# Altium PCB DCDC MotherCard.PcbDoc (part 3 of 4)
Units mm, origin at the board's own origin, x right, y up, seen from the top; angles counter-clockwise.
Board outline 252.5 x 130 mm, 6 copper layers (Top Layer, Layer 2, Layer 3, Layer 4, Layer 5, Bottom Layer), stack 1.582 mm thick; 322 components, 189 nets, 1077 pads, 1461 vias.
Unrouted connection lines stored in the file: 2.
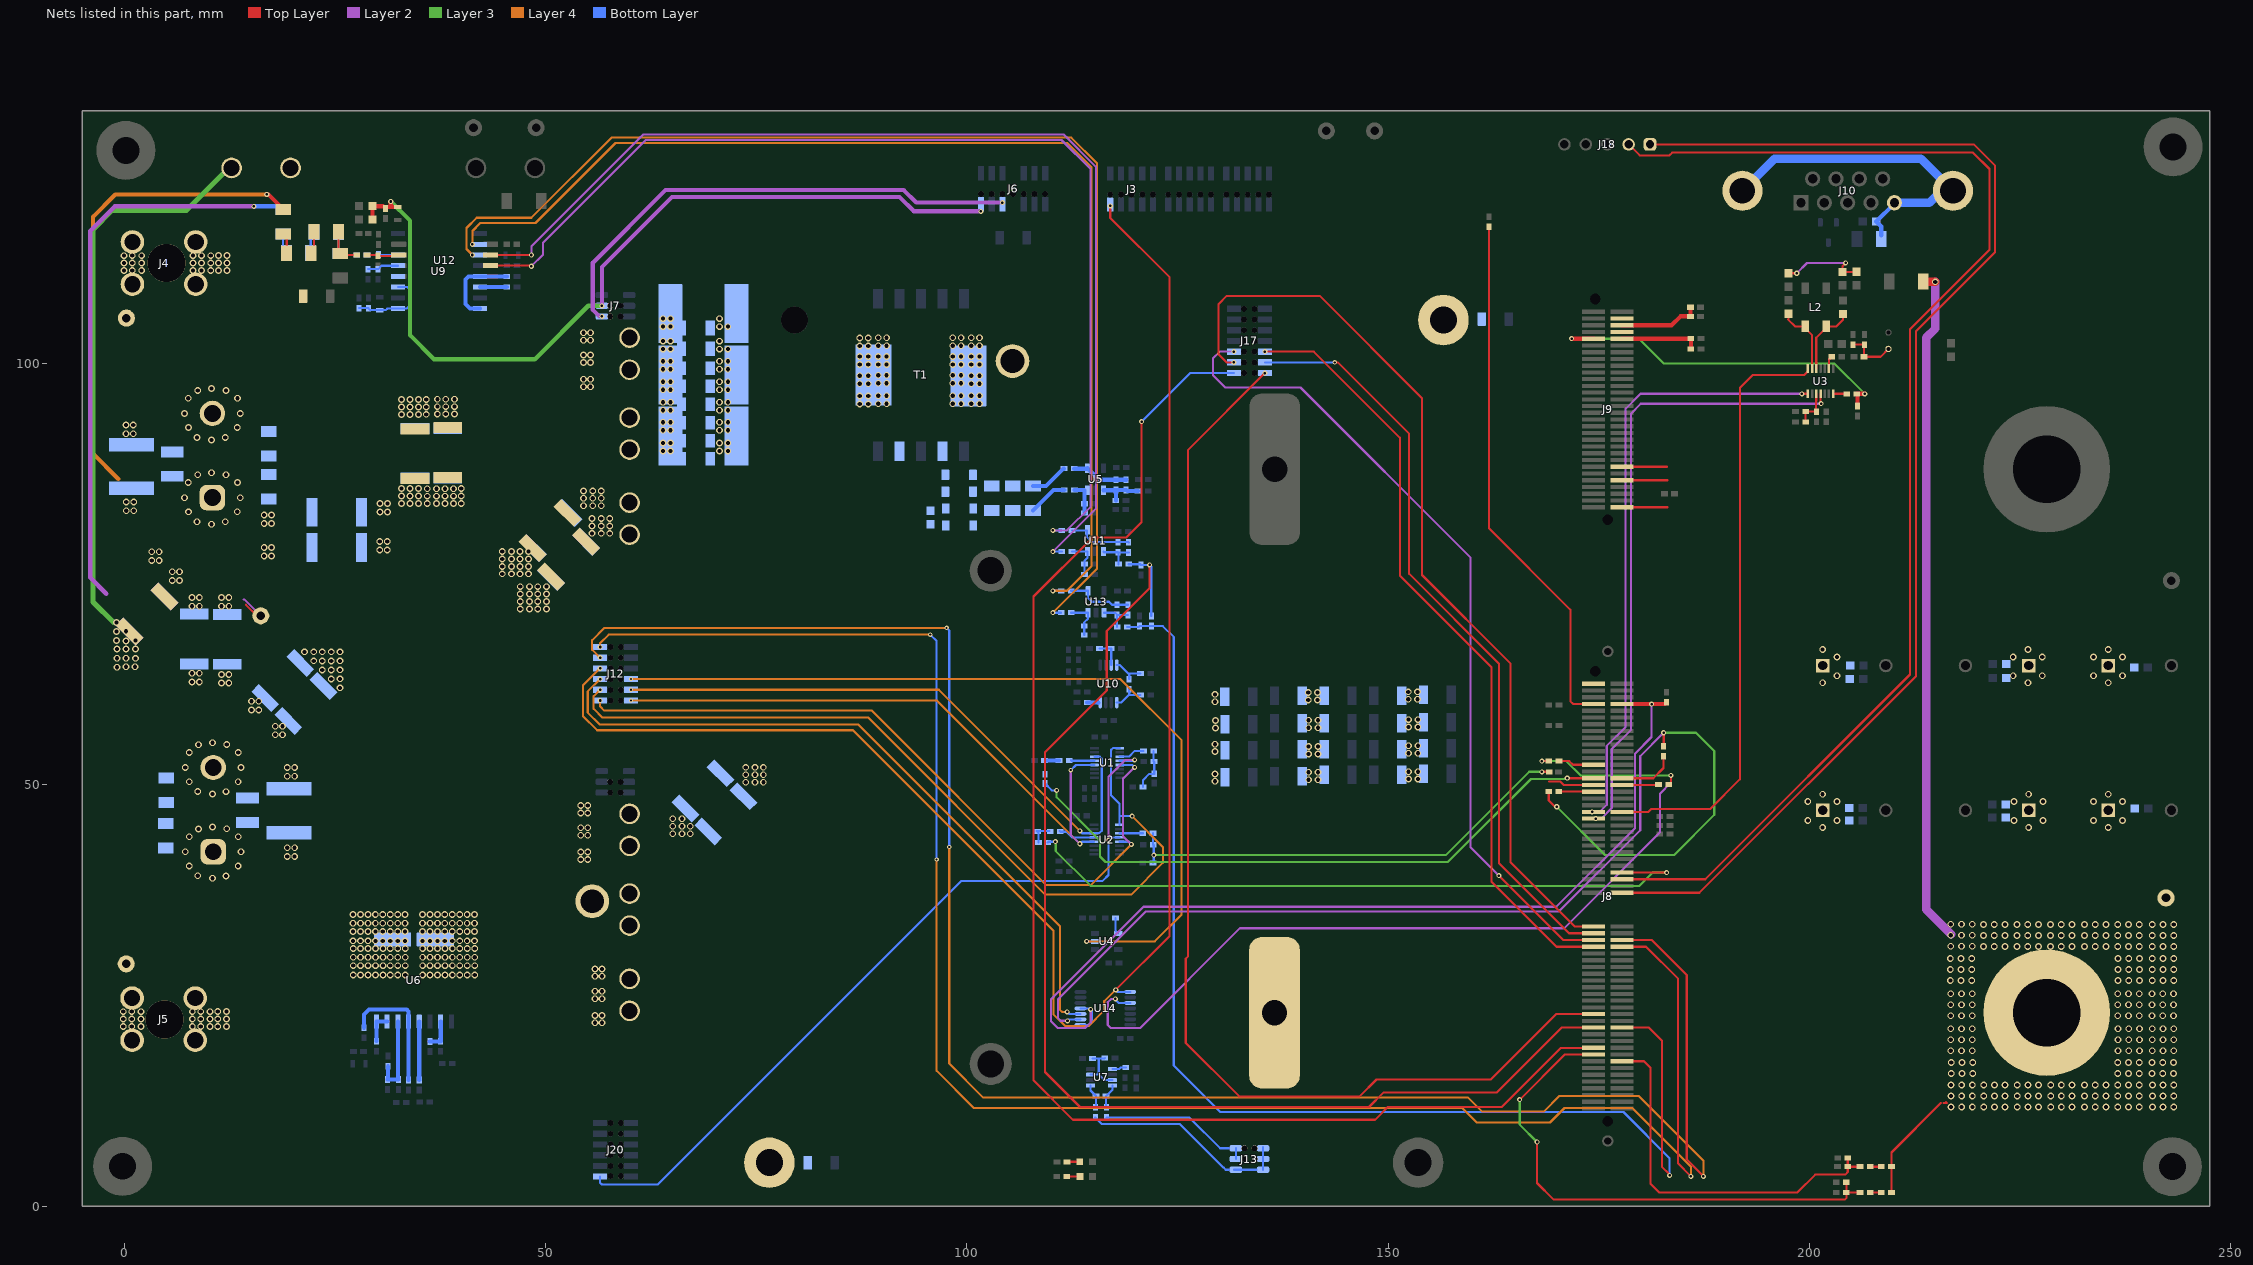
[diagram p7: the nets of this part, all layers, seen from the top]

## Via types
v1: diameter 0.8, hole 0.5, Top Layer to Bottom Layer, 1187 vias
v2: diameter 0.6, hole 0.3, Top Layer to Bottom Layer, 259 vias
v3: diameter 0.508, hole 0.254, Top Layer to Bottom Layer, 13 vias
v4: diameter 4.5, hole 4.5, Top Layer to Bottom Layer, 2 vias

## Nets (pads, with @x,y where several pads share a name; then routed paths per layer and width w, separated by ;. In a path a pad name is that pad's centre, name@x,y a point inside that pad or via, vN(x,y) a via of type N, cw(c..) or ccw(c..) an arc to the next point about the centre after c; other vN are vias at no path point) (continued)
LAG_OC_L: J20.2 U1.4 U2.4 | length 95.2
  Layer 2 w0.254: v2(116.809,43.458) 116.809,50.977 118.801,52.97 v2(119.905,52.97)
  Bottom Layer w0.254: J20.2@56.457,3.525 56.457,2.8 56.681,2.577 63.314,2.577 99.358,38.62 116.109,38.62 116.809,39.32 v2(116.809,43.458) 117.12,43.769 U2.4@118.087,43.769 ; U1.4@118.139,52.869 119.804,52.869 v2(119.905,52.97)
LAG_SW: pad.1@55.525,36.2 TP9.1 TP10.1
LEAD_EN_DRV: J12.6 U14.3 | length 83.7
  Layer 4 w0.254: v2(56.457,62.565) 55,61.107 55,58.59 56.415,57.175 87.115,57.175 111.024,33.266 111.024,23.325 111.274,23.075 v2(111.884,23.075)
  Bottom Layer w0.254: v2(111.884,23.075) 112.126,22.833 U14.3@113.477,22.833
LEAD_EN_DRV_MCU: R82.2 R83.1 U14.2 | length 136.6
  Top Layer w0.254: R82.2@169.048,49.206 169.056,49.198 169.056,48.16 169.798,47.417 v2(169.998,47.417) ; v2(182.675,56.2) 182.69,56.185 R83.1@182.69,54.606
  Layer 2 w0.254: v2(111.933,22.015) 111.135,22.015 110.795,22.355 110.795,24.538 121.232,34.975 170.24,34.975 179.9,44.635 179.9,53.425 v2(182.675,56.2)
  Layer 3 w0.254: v2(169.998,47.417) 175.718,41.698 183.932,41.698 188.692,46.458 188.692,54.033 186.525,56.2 v2(182.675,56.2)
  Bottom Layer w0.254: v2(111.933,22.015) 112.101,22.183 U14.2@113.477,22.183
LEAD_EN_ISO_12V: J3.1 J12.8 U14.8 | length 193.6
  Top Layer w0.254: v2(117.01,118.725) 117.01,117.283 124.052,110.24 124.052,32.082 v2(117.663,25.693)
  Layer 4 w0.254: v2(56.457,63.835) 54.442,61.819 54.442,58.167 56.108,56.5 86.486,56.5 110.262,32.723 110.262,22.799 111.673,21.388 114.437,21.388 116.298,23.249 116.298,24.328 v2(117.663,25.693)
  Bottom Layer w0.254: v2(117.663,25.693) 117.923,25.433 U14.8@119.377,25.433
LEAD_EN_ISO_12V_1: J8.96 R13.1 | length 4.3
  Top Layer w0.254: R13.1@170.256,52.828 171.497,52.828 171.919,52.406 J8.96@174.354,52.406
LEAD_EN_ISO_12V_ALT: J8.89 R55.2 | length 4.3
  Top Layer w0.254: J8.89@177.754,50.006 182.049,50.006 R55.2@182.075,50.032
LEAD_EN_ISO_12V_MCU: R13.2 R55.1 U14.10 | length 106.2
  Top Layer w0.254: v2(168.227,52.828) R13.2@169.056,52.828 ; R55.1@183.275,50.032 183.536,50.293 v2(183.536,51.136)
  Layer 2 w0.254: v2(117.627,24.605) 117.111,24.605 116.719,24.213 116.719,21.517 117.069,21.166 120.566,21.166 132.393,32.993 170.871,32.993 182.25,44.372 182.25,48.972 183.536,50.257 v2(183.536,51.136)
  Layer 3 w0.254: v2(168.227,52.828) 171.121,52.828 172.813,51.136 v2(183.536,51.136)
  Bottom Layer w0.254: v2@117.719,24.428 118.014,24.133 U14.10@119.377,24.133
LEAD_GaN_FAULT: J12.5 U4.2 | length 102.6
  Layer 4 w0.254: v3(60.143,62.565) 60.149,62.558 100.309,62.558 118.233,62.558 125.475,55.316 125.475,34.621 122.296,31.443 v2(114.195,31.443)
  Bottom Layer w0.254: v2(114.195,31.443) U4.2@115.197,31.443
LEAD_HS_PWM: J8.49 J12.12 | length 221.2
  Top Layer w0.254: J8.49@177.754,30.806 180.594,30.806 184.4,27 184.4,5.068 v2(185.908,3.56)
  Layer 4 w0.254: v2(56.457,66.375) 56.457,66.808 57.486,67.837 v3(95.647,67.837) ; v3(96.4,41.15) 96.4,16.075 100.811,11.664 158.772,11.664 160.495,9.942 169.192,9.942 170.914,11.664 178.966,11.664 185.908,4.722 v2(185.908,3.56)
  Bottom Layer w0.254: v3(95.647,67.837) 96.4,67.084 v3(96.4,41.15)
LEAD_HS_TEMP: J12.1 U1.12 U2.12 | length 74.3
  Layer 2 w0.254: v3(112.327,51.757) 112.327,44.098 v2(113.4,43.025)
  Layer 4 w0.254: v3(60.143,60.025) 96.4,60.025 v2(113.4,43.025)
  Bottom Layer w0.254: v3(112.327,51.757) 112.939,52.369 U1.12@115.139,52.369 ; v2(113.4,43.025) 113.644,43.269 U2.12@115.087,43.269
LEAD_ISO_12V_L: C41.1 C44.1 J6.1 J7.3 pad.3@57.673,106.87 R30.1 R37.1 | length 102.5
  Top Layer w0.5: R37.1@29.452,117.132 R30.1@29.452,118.732 29.508,118.675 30.689,118.675 30.78,118.584 31.514,118.584 ; v2(31.618,119.246) 31.618,118.689 31.514,118.584 ; C41.1@32.462,118.584 31.514,118.584
  Layer 2 w0.5: v2(56.675,106.87) 56.675,111.457 64.993,119.775 92.005,119.775 93.695,118.085 v2(101.665,118.085)
  Layer 3 w0.5: v2(31.618,119.246) 33.892,116.972 33.892,103.381 36.748,100.525 48.718,100.525 55.063,106.87 v2(56.675,106.87)
LEAD_ISO_-5V_L: J6.5 J7.5 pad.3@57.673,105.6 | length 59.8
  Layer 2 w0.5: v2(56.675,105.6) 56.387,105.6 55.6,106.387 55.6,111.972 64.233,120.605 92.488,120.605 93.982,119.111 v2(104.205,119.111)
LEAD_LS_PWM: J8.51 J12.10 | length 228.7
  Top Layer w0.254: J8.51@177.754,31.606 181.269,31.606 185.425,27.45 185.425,5.543 v2(187.408,3.56)
  Layer 4 w0.254: v2(56.457,65.105) 55.523,66.039 55.523,67.192 56.977,68.646 v3(97.589,68.646) ; v3(97.892,42.638) 97.892,16.944 101.947,12.89 159.475,12.89 161.136,11.229 168.439,11.229 170.298,13.088 179.711,13.088 187.408,5.391 v2(187.408,3.56)
  Bottom Layer w0.254: v3(97.589,68.646) 97.892,68.342 v3(97.892,42.638)
LEAD_LS_TEMP: J12.3 U1.14 U2.14 | length 72.5
  Layer 4 w0.254: v3(60.143,61.295) 96.655,61.295 v2(113.4,44.55)
  Bottom Layer w0.254: v2(113.4,44.55) 113.681,44.269 U2.14@115.087,44.269 115.11,44.292 115.718,44.292 115.991,44.564 115.991,53.126 115.77,53.346 115.162,53.346 U1.14@115.139,53.369
LEAD_OC_H: J12.4 U1.1 U2.1 | length 99.8
  Layer 4 w0.254: v2(56.457,61.295) 55.7,60.537 55.7,59.027 56.727,58 88.275,58 109.283,36.992 119.496,36.992 123.254,40.75 123.254,42.641 v2(119.598,46.298)
  Bottom Layer w0.254: U2.1@118.087,45.269 118.087,46.298 ; U1.1@118.139,54.369 117.315,54.369 117.105,54.16 117.105,48.79 118.087,47.809 118.087,46.298 ; v2(119.598,46.298) 118.087,46.298
LEAD_OC_L: J12.2 U1.5 U2.5 | length 88.1
  Layer 2 w0.254: v2(119.505,42.943) 118.503,43.945 118.503,50.701 v2(119.892,52.09)
  Layer 4 w0.254: v2(56.457,60.025) 56.457,59.342 56.974,58.825 88.684,58.825 88.694,58.836 109.41,38.12 114.682,38.12 v2(119.505,42.943)
  Bottom Layer w0.254: U2.5@118.087,43.269 119.244,43.269 119.505,43.008 v2(119.505,42.943) ; U1.5@118.139,52.369 119.613,52.369 v2(119.892,52.09)
LEAD_SW: C7.2 C8.2 C9.2 C10.2 C13.2 C18.2 C46.1 C47.1 C72.1 R2.1 R3.1 TP1.1 TP2.1
  other v1: 63.928,89.625 64.825,89.625 63.928,90.575 64.825,90.575 63.928,92.1 64.825,92.1 63.928,93.05 64.825,93.05 63.928,94.475 64.825,94.475 63.928,95.425 64.825,95.425 63.928,96.9 64.825,96.9 63.928,97.85 64.825,97.85 63.928,99.325 64.825,99.325 63.928,100.275 64.825,100.275 63.928,101.725 64.825,101.725 63.928,102.675 64.825,102.675 63.928,104.394 64.825,104.394 63.928,105.344 64.825,105.344
LEAD_SW_R: C7.1 C8.1 C9.1 C10.1 C13.1 C18.1 C46.2 C47.2 C72.2 R2.2 R3.2 T1.12
  other v1: 70.628,89.625 71.628,89.625 70.628,90.575 71.628,90.575 70.628,92.1 71.628,92.1 70.628,93.05 71.628,93.05 70.628,94.475 71.628,94.475 87.275,95.207 88.275,95.207 89.468,95.25 90.468,95.25 70.628,95.425 71.628,95.425 87.275,96.157 88.275,96.157 89.468,96.2 90.468,96.2 70.628,96.9 71.628,96.9 87.275,97.608 88.275,97.608 89.468,97.679 90.468,97.679 70.628,97.85 71.628,97.85 87.275,98.558 88.275,98.558 89.468,98.629 90.468,98.629 70.628,99.325 71.628,99.325 87.275,99.911 88.275,99.911 89.468,99.911 90.468,99.911 70.628,100.275 71.628,100.275 87.275,100.861 88.275,100.861 89.468,100.861 90.468,100.861 70.628,101.725 71.628,101.725 87.275,102.1 88.275,102.1 89.468,102.125 90.468,102.125 70.628,102.675 87.275,103.05 88.275,103.05 89.468,103.075 90.468,103.075 70.628,104.394 71.628,104.394 70.628,105.344
"NC U4": U9.4
NetC1_2: C1.2 C3.2 C6.2 R6.1 R15.2 R16.1 R128.2 R129.1
  other v1: 10.458,48.918 12.065,49.211 8.715,49.218 7.718,50.386 13.508,50.393 19.33,51.043 20.212,51.043 7.233,52.068 13.858,52.068 19.33,52.068 20.212,52.068 7.695,53.861 13.533,53.868 8.808,54.786 12.158,54.793 10.458,55.021 17.9,55.95 18.782,55.95 17.9,56.975 18.782,56.975 15.082,58.9 15.964,58.9 15.082,59.925 15.964,59.925 11.525,62.1 12.407,62.1 8.023,62.226 8.905,62.226 11.525,63.125 12.407,63.125 8.023,63.251 8.905,63.251
NetC20_1: C20.1 R10.1 R80.1 U3.3 | length 4.6
  Top Layer w0.254: R10.1@199.538,93.103 R80.1@199.538,94.338 200.766,94.338 200.752,94.353 200.752,95.508 200.8,95.556 U3.3@200.8,96.425
NetC21_1: C21.1 R18.1 R21.2 | length 10.2
  Top Layer w0.254: R21.2@197.479,110.721 197.492,110.734 v2(198.477,110.734) ; v2(204.284,111.953) 203.925,111.595 R18.1@203.925,110.883 205.508,110.883 C21.1@205.55,110.925
  Layer 2 w0.254: v2(198.477,110.734) 199.697,111.953 v2(204.284,111.953)
NetC24_1: C24.1 R24.2 R27.1 R67.1 U5.1 | length 5.4
  Bottom Layer w0.5: U5.1@116.209,84.988 R24.2@117.648,84.988 ; R27.1@117.674,83.772 117.674,84.961 R24.2@117.648,84.988 ; R67.1@120.31,84.878 119.042,84.878 C24.1@118.903,85.017 R24.2@117.678,85.017 R24.2@117.648,84.988
NetC24_2: C24.2 R24.1 R25.2 U5.4 | length 6.8
  Bottom Layer w0.5: R25.2@112.724,87.537 114.258,87.537 U5.4@114.309,87.588 115.679,86.217 R24.1@117.678,86.217 C24.2@118.903,86.217
NetC35_1: C35.1 R31.2 R32.2 U5.3 | length 3.9
  Bottom Layer w0.5: R31.2@112.754,85.002 113.88,85.002 113.943,84.939 R32.2@113.943,83.378 113.943,82.281 C35.1@113.94,82.278
NetC45_1: C45.1 R47.2 U7.8 | length 2.9
  Bottom Layer w0.254: R47.2@116.555,11.739 116.517,11.776 C45.1@116.517,13.091 117.269,13.843 U7.8@117.269,14.332
NetC45_2: C45.2 R52.2 U7.1 | length 2.9
  Bottom Layer w0.254: U7.1@114.669,14.332 114.669,13.74 C45.2@115.317,13.091 115.317,11.824 R52.2@115.231,11.739
NetC55_1: C55.1 R73.2 U10.1 | length 3.9
  Bottom Layer w0.254: U10.1@117.773,59.769 118.289,59.769 119.191,60.672 ; C55.1@119.258,61.358 119.258,60.739 119.191,60.672 ; R73.2@120.605,60.672 119.191,60.672
NetC55_2: C55.2 R74.2 U10.8 | length 3.9
  Bottom Layer w0.254: U10.8@117.773,64.219 118.169,64.219 119.177,63.211 119.258,63.211 ; C55.2@119.258,62.558 119.258,63.211 ; R74.2@120.608,63.211 119.258,63.211
NetC70_1: C70.1 D13.2 R35.2 | length 3
  Bottom Layer w0.254: D13.2@108.479,43.166 108.479,44.346 108.291,44.533 R35.2@109.81,44.533
NetC71_1: C71.1 D14.2 R14.1 R36.2 | length 54.6
  Top Layer w0.254: v2(168.227,51.566) D14.2@169.106,51.566
  Layer 3 w0.254: v2(122.175,41.675) 156.825,41.675 166.716,51.566 v2(168.227,51.566)
  Bottom Layer w0.254: R14.1@122.069,40.735 122.175,40.841 v2(122.175,41.675) 122.175,42.842 C71.1@122.109,42.908 122.069,42.948 R36.2@122.069,44.269
NetC73_1: C73.1 R92.1 R93.2 TP3.1 | length 6
  Top Layer w0.254: C73.1@205.179,102.253 R92.1@206.496,102.253 206.461,102.218 R93.2@206.461,100.822 208.429,100.822 TP3.1@209.36,101.753
NetC78_1: C78.1 U9.13 U9.16 | length 9.9
  Bottom Layer w0.5: U9.16@42.218,106.546 41.038,106.546 40.493,107.091 40.493,110.006 40.843,110.356 U9.13@42.218,110.356 C78.1@45.393,110.356
NetC79_1: C79.1 C80.1 C81.1 U9.1 U9.3 | length 9.8
  Bottom Layer w0.254: C79.1@27.843,106.591 C81.1@28.968,106.591 29.205,106.354 C80.1@30.293,106.354 31.04,106.354 31.232,106.546 U9.1@32.468,106.546 33.523,106.546 33.843,106.866 33.843,108.854 33.612,109.086 U9.3@32.468,109.086
NetC84_1: C84.1 C85.1 U9.5 | length 3.7
  Bottom Layer w0.254: C84.1@28.943,111.216 C85.1@30.118,111.216 30.528,111.626 U9.5@32.468,111.626
NetC86_1: C86.1 R51.1 U9.6 | length 3.7
  Bottom Layer w0.254: R51.1@28.786,112.896 30.098,112.896 C86.1@30.168,112.966 30.238,112.896 U9.6@32.468,112.896
NetC87_1: C87.1 R59.1 R61.1 U13.4 | length 7.9
  Bottom Layer w0.254: R61.1@112.382,73.043 U13.4@114.382,73.043 114.382,72.166 114.806,71.743 116.857,71.743 117.215,71.386 R59.1@117.829,71.386 C87.1@119.108,71.386
NetC87_2: C87.2 R59.2 R113.1 U13.1 | length 4.4
  Bottom Layer w0.254: U13.1@116.282,70.443 117.572,70.443 R59.2@117.829,70.186 ; R113.1@117.829,68.754 R59.2@117.829,70.186 ; C87.2@119.108,70.186 R59.2@117.829,70.186
NetC91_1: C91.1 R66.1 R69.2 U13.3 | length 4.9
  Bottom Layer w0.254: R66.1@112.382,70.443 U13.3@114.382,70.443 114.382,69.76 113.921,69.298 C91.1@113.921,68.855 R69.2@113.921,67.783
NetC97_1: C97.1 R107.1 U12.2 | length 3.9
  Top Layer w0.254: R107.1@28.795,112.896 30.017,112.896 C97.1@30.118,112.795 32.462,112.795 U12.2@32.568,112.901
NetC98_1: C98.1 R60.1 R109.1 U11.4 | length 7.8
  Bottom Layer w0.254: R60.1@112.461,80.218 114.226,80.218 114.226,79.442 114.851,78.817 C98.1@117.938,78.817 119.177,78.817 R109.1@119.198,78.796
NetC98_2: C98.2 R109.2 R112.1 U11.1 | length 4.4
  Bottom Layer w0.254: U11.1@116.205,77.697 116.284,77.617 C98.2@117.938,77.617 C98.2@117.959,77.596 ; R112.1@117.992,76.203 117.992,77.563 C98.2@117.959,77.596 ; R109.2@119.198,77.596 C98.2@117.959,77.596
NetC102_1: C102.1 R65.1 R116.2 U11.3 | length 4.7
  Bottom Layer w0.254: R65.1@112.461,77.697 U11.3@114.305,77.697 114.305,76.966 113.96,76.621 R116.2@113.96,76.211 C102.1@113.96,74.993
NetC103_1: C103.1 R111.2 R114.2 U6.8 | length 9.8
  Bottom Layer w0.5: R111.2@31.3,16.625 31.3,15.132 C103.1@31.229,15.06 R114.2@32.52,15.06 32.463,15.118 U6.8@32.463,21.925
NetC107_1: C107.1 D11.2 R125.2 | length 2.8
  Bottom Layer w0.254: D11.2@109.259,51.556 109.259,52.724 C107.1@109.405,52.869
  Bottom Layer w0.5: C107.1@109.555,52.89 R125.2@110.936,52.89
NetC108_1: C108.1 D12.2 R130.1 R131.2 | length 5.2
  Bottom Layer w0.254: R130.1@120.89,49.764 120.89,50.578 121.636,51.324 D12.2@122.226,51.324 122.226,52.706 122.16,52.772 R131.2@122.16,54.043
NetD1_1: D1.1 R8.1 | length 1.5
  Top Layer w0.254: R8.1@111.886,5.279 113.386,5.279 D1.1@113.392,5.285
NetD2_1: D2.1 R9.1 | length 1.6
  Top Layer w0.254: R9.1@111.849,3.523 D2.1@113.412,3.523
NetD6_1: D6.1 D8.2 R38.2 T1.4
NetD6_2: D6.2 D7.2 R25.1 R28.2 R29.2 R39.2 | length 4.5
  Bottom Layer w0.5: R28.2@107.84,85.479 109.387,85.479 111.446,87.537 R25.1@111.524,87.537
NetD7_1: D7.1 D9.2 R38.1 T1.2
NetD8_1: D8.1 D9.1 R28.1 R29.1 R31.1 R39.1 | length 4.7
  Bottom Layer w0.5: R28.1@107.84,82.579 110.263,85.002 R31.1@111.554,85.002
NetJ8_88: J8.88 R82.1 | length 4.1
  Top Layer w0.254: R82.1@170.248,49.206 J8.88@174.354,49.206
NetJ8_91: J8.91 R83.2 | length 6.8
  Top Layer w0.254: J8.91@177.754,50.806 181.468,50.806 182.675,52.013 182.675,53.391 R83.2@182.69,53.406
NetL1_2: L1.2 U6.9 U6.10 | length 3.6
  Bottom Layer w0.5: L1.2@29.923,19.6 U6.10@29.923,21.925 U6.9@31.193,21.925
NetL2_1: L2.1 R22.1 U3.13 | length 8.4
  Top Layer w0.254: 197.479,105.223 198.28,104.421 L2.1@199.479,104.421 199.479,104.205 200.3,103.385 U3.13@200.3,99.425 ; 197.479,105.223 R22.1@197.479,105.946
NetL2_2: L2.2 R17.1 U3.12 | length 8.5
  Top Layer w0.254: U3.12@200.8,99.425 200.8,103.087 201.979,104.266 L2.2@201.979,104.421 203.202,104.421 203.954,105.173 R17.1@203.954,105.896
NetR4_1: R4.1 R6.2
NetR5_1: R5.1 R7.2
NetR34_1: R34.1 U4.4 | length 2
  Bottom Layer w0.254: R34.1@117.627,34.224 117.627,32.713 U4.4@117.947,32.393
NetR35_1: R35.1 U2.13 | length 4.4
  Bottom Layer w0.254: R35.1@111.01,44.533 111.089,44.455 111.793,44.455 112.479,43.769 U2.13@115.087,43.769
NetR36_1: R36.1 U2.3 | length 2.8
  Bottom Layer w0.254: U2.3@118.087,44.269 R36.1@120.869,44.269
NetR40_1: R40.1 U6.6 | length 6.9
  Bottom Layer w0.5: R40.1@35.003,14.993 U6.6@35.003,21.925
NetR42_2: R42.2 U9.14 | length 3.2
  Bottom Layer w0.5: U9.14@42.218,109.086 R42.2@45.393,109.086
NetR43_2: R43.2 R44.1 | length 2.7
  Bottom Layer w0.254: R43.2@18.829,115.636 18.829,113.522 R44.1@19.22,113.131
NetR44_2: R44.2 R45.1 | length 2.6
  Bottom Layer w0.254: R44.2@22.12,113.131 22.12,115.235 R45.1@22.501,115.616
NetR45_2: R45.2 R51.2 R56.2 | length 4.6
  Bottom Layer w0.254: R45.2@25.401,115.616 25.401,113.298 R56.2@25.618,113.081 ; R56.2@25.673,113.136 25.913,112.896 R51.2@27.586,112.896
NetR54_2: R54.2 R58.1 U7.3 U7.7 | length 6.3
  Bottom Layer w0.254: U7.3@114.669,15.632 115.646,15.632 ; R58.1@114.915,17.53 115.614,17.53 ; R54.2@116.366,17.582 116.314,17.53 115.614,17.53 ; U7.7@117.269,14.982 116.296,14.982 115.646,15.632 ; 115.614,17.53 115.646,17.499 115.646,15.632
NetR62_1: R62.1 U7.5 | length 1.7
  Bottom Layer w0.254: U7.5@117.269,16.282 118.055,16.282 118.231,16.458 R62.1@118.85,16.458
NetR70_2: R70.2 U3.7 | length 1.6
  Top Layer w0.254: U3.7@202.8,96.425 R70.2@204.4,96.425
NetR71_2: R71.2 U3.9 | length 1.5
  Top Layer w0.254: U3.9@202.3,99.425 202.3,100.488 R71.2@202.634,100.822
NetR75_2: R75.2 R78.1 U10.7 | length 3.4
  Bottom Layer w0.254: R75.2@115.739,66.178 R78.1@117.139,66.178 117.123,66.162 U10.7@117.123,64.219
NetR76_1: R76.1 U10.4 | length 1.3
  Bottom Layer w0.5: R76.1@114.266,59.791 115.561,59.791 115.582,59.769 115.59,59.769
NetR79_1: R79.1 R110.1 U6.7 | length 15.3
  Bottom Layer w0.5: R79.1@28.43,21.194 28.43,22.755 29.025,23.35 33.508,23.35 33.733,23.125 U6.7@33.733,21.925 R110.1@33.733,14.993
NetR81_1: R81.1 R99.2 | length 1.4
  Top Layer w0.254: R99.2@207.197,4.7 208.528,4.7 R81.1@208.55,4.722
NetR98_1: R98.1 R100.2 | length 1.3
  Top Layer w0.254: R100.2@207.197,1.629 R98.1@208.515,1.629
NetR103_1: R103.1 R115.1 U6.4 | length 3.6
  Bottom Layer w0.5: R103.1@36.25,19.562 37.508,19.562 37.543,19.596 U6.4@37.543,21.925
NetR104_2: R104.2 R105.1 | length 2.8
  Top Layer w0.254: R104.2@18.729,115.616 19.27,115.074 R105.1@19.27,113.088
NetR105_2: R105.2 R106.1 | length 2.7
  Top Layer w0.254: R105.2@22.17,113.088 22.501,113.419 R106.1@22.501,115.636
NetR106_2: R106.2 R107.2 R108.2 | length 4.7
  Top Layer w0.254: R106.2@25.401,115.636 25.401,113.298 R108.2@25.618,113.081 25.803,112.896 R107.2@27.595,112.896
NetR125_1: R125.1 U1.13 | length 2.9
  Bottom Layer w0.254: R125.1@112.328,52.97 112.429,52.869 U1.13@115.139,52.869
NetR131_1: R131.1 U1.3 | length 3.1
  Bottom Layer w0.254: U1.3@118.139,53.369 119.231,53.369 119.905,54.043 R131.1@120.96,54.043
nSTB: J8.81 U3.14 | length 71.3
  Top Layer w0.254: J8.81@177.754,46.806 180.89,46.806 181.229,47.145 188.205,47.145 191.725,50.665 191.725,97.119 193.254,98.648 199.378,98.648 199.8,99.07 U3.14@199.8,99.425
PGND: C4.2 C5.2 C56.2 J4.1 J4.3 J4.4 J4.6 PGND.1 R7.1 R15.1 R19.2 R119.1 R120.2 R121.2 R126.2 R128.1 TP7.1 TP8.1
  other v1: 25.6,61.525 24.545,62.588 25.61,62.593 23.482,63.657 24.545,63.657 25.61,63.661 22.48,64.729 23.482,64.727 24.545,64.727 25.61,64.729 21.373,65.797 22.482,65.797 23.482,65.797 24.545,65.797 25.61,65.797 10.358,90.943 8.615,91.243 11.965,91.236 0.187,91.689 1.069,91.689 7.618,92.411 13.408,92.418 0.187,92.714 1.069,92.714 32.892,93.971 33.892,93.971 34.917,93.971 35.834,93.984 37.152,94.018 38.152,94.018 39.177,94.018 7.133,94.093 13.758,94.093 32.892,94.853 33.892,94.853 34.917,94.853 35.834,94.866 37.152,94.9 38.152,94.9 39.177,94.9 32.892,95.735 33.892,95.735 34.917,95.735 35.834,95.748 37.152,95.782 38.152,95.782 39.177,95.782 7.595,95.886 13.433,95.893 8.708,96.811 12.058,96.818 10.358,97.046 54.5,97.27 55.335,97.27 54.5,98.152 55.335,98.152 54.5,100.138 55.335,100.138 54.5,101.02 55.335,101.02 54.5,102.784 55.335,102.784 54.5,103.666 55.335,103.666 -0.047,111.059 0.953,111.059 2.053,111.059 8.153,111.059 9.153,111.059 10.253,111.059 11.169,111.071 12.194,111.071 -0.047,111.94 0.953,111.94 2.053,111.94 8.153,111.94 9.153,111.94 10.253,111.94 11.169,111.953 12.194,111.953 -0.047,112.822 0.953,112.822 2.053,112.822 8.153,112.822 9.153,112.822 10.253,112.822 11.169,112.835 12.194,112.835
  other v4: 4.994,111.953
PMIC_COMP1_IN+: J9.175 R91.1 R96.2 | length 9.6
  Top Layer w0.5: J9.175@177.754,104.563 183.614,104.563 184.666,105.615 R91.1@185.867,105.615 R96.2@185.867,106.696
PMIC_COMP1_IN-: J9.177
PMIC_COMP2_IN+: J9.171 R87.2 R95.1 | length 9.3
  Top Layer w0.5: J9.171@177.754,102.963 R95.1@185.822,102.963 ; R87.2@185.913,101.726 R95.1@185.913,102.972
PMIC_COMP2_IN-: J9.173
PMIC_SAFE_OUT1: J8.113 R50.1 U14.1 U14.4 | length 112.4
  Top Layer w0.5: J8.113@177.754,59.606 v2(181.244,59.606) 182.815,59.606 R50.1@183.015,59.806
  Layer 2 w0.254: v2(114.688,23.367) 114.688,21.843 114.011,21.166 110.761,21.166 109.977,21.95 109.977,24.57 120.957,35.55 169.945,35.55 179.275,44.88 179.275,53.721 181.244,55.69 v2(181.244,59.606)
  Bottom Layer w0.254: U14.1@113.477,21.533 114.543,21.533 114.804,21.794 114.804,23.25 v2(114.688,23.367) 114.572,23.483 U14.4@113.477,23.483
PMIC_WAKE1: J8.114 R97.1 | length 63.2
  Top Layer w0.254: R97.1@161.975,116.25 161.95,116.225 161.95,80.467 171.61,70.808 171.61,59.943 171.947,59.606 J8.114@174.354,59.606
PMIC_WAKE2: J9.172 R70.1 R94.2 | length 42.5
  Top Layer w0.5: v2(171.764,102.963) J9.172@174.354,102.963 ; R94.2@205.7,94.975 205.7,96.325 R70.1@205.6,96.425 v2(206.55,96.425)
  Layer 3 w0.254: v2(171.764,102.963) 179.762,102.963 182.7,100.025 202.95,100.025 v2(206.55,96.425)
PROFILING1: J8.57 J18.1 | length 152
  Top Layer w0.254: J8.57@177.754,37.206 186.919,37.206 212.65,62.937 212.65,103.88 222.025,113.255 222.025,123.488 219.488,126.025 J18.1@181.067,126.025
PROFILING2: J8.61 J18.2 | length 152.4
  Top Layer w0.254: J8.61@177.754,38.806 187.616,38.806 211.925,63.115 211.925,104.094 221.35,113.519 221.35,123.1 219.4,125.05 183.7,125.05 183.375,124.725 179.827,124.725 J18.2@178.527,126.025
RST: J8.120
RxD: J8.80 U3.4 | length 74.5
  Top Layer w0.254: U3.4@201.3,96.425 201.3,95.327 v2(201.379,95.248)
  Layer 2 w0.254: v2(174.623,46.006) 175.266,46.006 176.522,47.262 176.522,54.262 178.819,56.559 178.819,94.094 179.973,95.248 v2(201.379,95.248)
SHIELD_GND: C23.1 J10.5 J10.10 J10.11 R23.2 | length 40.7
  Bottom Layer w0.5: C23.1@208.509,115.25 208.509,116.27 R23.2@207.909,116.87 210.064,119.025 J10.5@210.064,119.095
  Bottom Layer w1: J10.10@192.029,120.515 195.838,124.325 213.209,124.325 J10.11@217.019,120.515 215.647,120.515 214.227,119.095 J10.5@210.064,119.095
SHIELD_GND1: pad.1@76.55,5.175 R33.1
SHIELD_GND2: pad.1@156.55,105.175 R77.1
SR1_HS_PWM: J8.50 J17.5 | length 92.7
  Top Layer w0.254: v2(135.36,101.425) 141.165,101.425 151.376,91.213 151.376,74.863 162.233,64.006 162.233,38.536 169.963,30.806 J8.50@174.354,30.806
SR1_LS_PWM: J8.52 J17.6 | length 97.8
  Top Layer w0.254: v2(163.138,39.241) 170.773,31.606 J8.52@174.354,31.606
  Layer 2 w0.254: v2(131.675,101.425) 130.006,101.425 129.209,100.628 129.209,98.618 130.652,97.175 139.579,97.175 159.74,77.014 159.74,42.639 v2(163.138,39.241)
SR2_HS_PWM: J8.54 J17.3 | length 89.5
  Top Layer w0.254: v3(143.655,100.155) 143.995,100.155 152.483,91.667 152.483,75.052 163.138,64.397 163.138,40.724 171.456,32.406 J8.54@173.225,32.406
  Bottom Layer w0.254: J17.3@135.36,100.155 v3(143.655,100.155)
SR2_LS_PWM: J8.56 J17.4 | length 110.2
  Top Layer w0.254: v2(131.675,100.155) 130.81,100.155 129.854,101.11 129.854,107.059 130.842,108.047 141.863,108.047 154,95.91 154,74.925 164.525,64.4 164.525,40.797 172.117,33.206 J8.56@174.354,33.206
T_HV_1: D13.1 J8.63 | length 81.9
  Top Layer w0.254: J8.63@177.754,39.606 v2(183.029,39.606)
  Layer 3 w0.254: v2@110.547,43.008 110.547,42.152 114.674,38.025 179.819,38.025 181.4,39.606 v2(183.029,39.606)
  Bottom Layer w0.254: D13.1@109.579,43.166 109.682,43.269 v2(110.504,43.269)
T_HV_2: D11.1 J8.92 | length 74.7
  Top Layer w0.254: v2(171.242,50.806) J8.92@174.354,50.806
  Layer 3 w0.254: v2(110.641,49.365) 110.641,48.527 115.782,43.386 115.782,41.504 116.436,40.85 157.075,40.85 166.942,50.717 171.153,50.717 v2(171.242,50.806)
  Bottom Layer w0.254: D11.1@109.259,50.167 110.061,49.365 v2(110.641,49.365)
T_LV_1: J8.30 J17.1 | length 138.4
  Top Layer w0.254: v2(135.36,98.885) 126.25,89.775 126.25,29.667 125.968,29.385 125.968,19.381 132.299,13.05 146.598,13.05 148.604,15.056 162.156,15.056 169.906,22.806 J8.30@174.354,22.806
T_LV_2: J8.20 J17.2 | length 171.1
  Top Layer w0.254: v2(120.725,93.125) 120.725,81.172 118.925,79.372 114.913,79.372 107.9,72.359 107.9,14.947 112.575,10.272 148.437,10.272 149.944,11.779 163.472,11.779 170.499,18.806 J8.20@174.354,18.806
  Bottom Layer w0.254: v2(120.725,93.125) 126.485,98.885 J17.2@131.675,98.885
test1: J8.90 | length 5.4
  Top Layer w0.254: 169.106,50.414 170.402,50.414 170.81,50.006 J8.90@174.354,50.006
test2: J9.121 | length 5.3
  Top Layer w0.254: J9.121@177.785,82.963 183.103,82.963
test3: J9.129 | length 5.3
  Top Layer w0.254: J9.129@177.785,86.163 183.103,86.163
test4: J9.133 | length 5.3
  Top Layer w0.254: J9.133@177.754,87.763 183.072,87.763
TxD: J8.82 U3.1 | length 72.4
  Top Layer w0.254: v2(199.077,96.425) U3.1@199.8,96.425
  Layer 2 w0.254: v2(174.202,46.806) 175.087,46.806 175.936,47.654 175.936,54.636 178.175,56.875 178.175,94.665 179.935,96.425 v2(199.077,96.425)
V_HV_1: C90.1 J8.25 R68.1 R113.2 | length 144.1
  Top Layer w0.254: J8.25@177.754,21.206 180.943,21.206 182.475,19.674 182.475,4.7 183.383,3.792 v2(183.383,3.669)
  Bottom Layer w0.254: R113.2@119.029,68.754 120.398,68.754 C90.1@120.499,68.855 R68.1@121.88,68.855 123.254,68.855 124.535,67.574 124.535,16.715 130.063,11.187 177.913,11.187 183.383,5.717 v2(183.383,3.669)
V_HV_2: C101.1 J8.26 R68.2 R112.2 | length 144.7
  Top Layer w0.254: v2(121.67,76.113) 121.67,73.361 116.591,68.282 116.591,61.203 109.255,53.867 109.255,15.939 113.415,11.779 147.716,11.779 149.423,13.485 162.848,13.485 170.569,21.206 J8.26@174.354,21.206
  Bottom Layer w0.254: R112.2@119.192,76.203 120.573,76.203 C101.1@120.662,76.113 v2(121.67,76.113) 121.88,75.903 R68.2@121.88,70.055
V_LV_1: C92.1 J8.15 R99.1 R101.2 | length 45.5
  Top Layer w0.254: J8.15@177.754,17.206 180.344,17.206 181.125,16.425 181.125,2.658 182.154,1.629 198.55,1.629 200.681,3.76 204.224,3.76 204.526,4.062 C92.1@204.526,4.7 ; R101.2@204.534,5.751 204.534,4.708 C92.1@204.526,4.7 ; R99.1@205.997,4.7 C92.1@204.526,4.7
V_LV_2: C93.1 J8.18 R100.1 R102.2 | length 62.8
  Top Layer w0.254: v2(165.598,12.656) 170.948,18.006 J8.18@174.354,18.006 ; v2(167.658,7.628) 167.658,2.759 169.592,0.825 204.224,0.825 204.365,0.966 C93.1@204.365,1.629 ; R102.2@204.365,2.854 C93.1@204.365,1.629 ; R100.1@205.997,1.629 C93.1@204.365,1.629
  Layer 3 w0.254: v2(165.598,12.656) 165.598,9.688 v2(167.658,7.628)
VBAT: C2.1 C11.1 C12.1 C14.1 C15.1 C16.1 C17.1 C25.1 C26.1 C27.1 C28.1 C31.1 C32.1 C33.1 C34.1 C36.1 C37.1 C38.1 C39.1 C40.1 C43.1 C48.1 C49.1 C50.1 C57.1 C58.1 C59.1 C60.1 C61.1 C62.1 C63.1 C64.1 C65.1 C66.1 C67.1 C68.1 D5.2 J13.2 J13.4 J13.5 J13.6 pad.1@228.15,22.975 pad.2@136.5,22.975 pad.3@134.143,5.61 pad.3@134.143,6.88 R52.1 R81.2 R98.2 VOUT.1 | length 118
  Top Layer w0.254: R98.2@209.75,1.594 R98.2@209.715,1.629 209.715,4.693 R81.2@209.721,4.7 209.721,6.384 215.587,12.25 ; 215.909,12.25 216.275,12.25 216.175,12.35 216.175,12.375
  Top Layer w1: D5.2@213.516,109.757 213.566,109.706 v1(214.927,109.706)
  Layer 2 w1: v1(214.927,109.706) 214.927,104.177 213.85,103.1 213.85,35.224 v1@216.814,32.26
  Bottom Layer w0.254: R52.1@115.231,10.539 116.004,9.766 125.265,9.766 130.449,4.583 130.476,4.583 130.719,4.34 131.115,4.34 ; J13.5@131.687,4.34 132.115,4.34 134.345,4.34 ; J13.6@135.145,4.34 J13.2@135.145,7.03
  other v1: 216.775,11.794 218.048,11.794 219.322,11.794 220.661,11.784 221.935,11.784 223.208,11.784 224.636,11.784 225.91,11.784 227.183,11.784 228.611,11.784 229.885,11.784 231.158,11.784 232.636,11.784 233.91,11.784 235.183,11.784 236.586,11.784 237.86,11.784 239.133,11.784 240.686,11.784 241.959,11.784 243.232,11.784 220.661,13.087 221.935,13.087 223.208,13.087 224.636,13.087 225.91,13.087 227.183,13.087 228.611,13.087 229.885,13.087 231.158,13.087 232.636,13.087 233.91,13.087 235.183,13.087 236.586,13.087 237.86,13.087 239.133,13.087 240.686,13.087 241.959,13.087 243.232,13.087 216.775,13.097 218.048,13.097 219.322,13.097 216.775,14.4 218.048,14.4 219.322,14.4 220.661,14.39 221.935,14.39 223.208,14.39 224.636,14.39 225.91,14.39 227.183,14.39 228.611,14.39 229.885,14.39 231.158,14.39 232.636,14.39 233.91,14.39 235.183,14.39 236.586,14.39 237.86,14.39 239.133,14.39 240.686,14.39 241.959,14.39 243.232,14.39 216.816,15.747 218.09,15.747 219.363,15.747 236.575,15.747 237.848,15.747 239.122,15.747 240.649,15.747 241.923,15.747 243.196,15.747 216.816,17.05 218.09,17.05 219.363,17.05 236.575,17.05 237.848,17.05 239.122,17.05 240.649,17.05 241.923,17.05 243.196,17.05 216.75,18.469 218.023,18.469 219.297,18.469 236.6,18.469 237.873,18.469 239.147,18.469 240.674,18.469 241.948,18.469 243.221,18.469 216.75,19.772 218.023,19.772 219.297,19.772 236.6,19.772 237.873,19.772 239.147,19.772 240.674,19.772 241.948,19.772 243.221,19.772 216.75,21.075 218.023,21.075 219.297,21.075 236.6,21.075 237.873,21.075 239.147,21.075 240.674,21.075 241.948,21.075 243.221,21.075 216.75,22.619 218.023,22.619 219.297,22.619 236.575,22.619 237.848,22.619 239.122,22.619 240.649,22.619 241.923,22.619 243.196,22.619 216.75,23.922 218.023,23.922 219.297,23.922 236.575,23.922 237.848,23.922 239.122,23.922 240.649,23.922 241.923,23.922 243.196,23.922 216.75,25.225 218.023,25.225 219.297,25.225 236.575,25.225 237.848,25.225 239.122,25.225 240.649,25.225 241.923,25.225 243.196,25.225 216.711,26.794 217.985,26.794 219.258,26.794 236.6,26.794 237.873,26.794 239.147,26.794 240.674,26.794 241.948,26.794 243.221,26.794 216.711,28.097 217.985,28.097 219.258,28.097 236.6,28.097 237.873,28.097 239.147,28.097 240.674,28.097 241.948,28.097 243.221,28.097 216.711,29.4 217.985,29.4 219.258,29.4 236.6,29.4 237.873,29.4 239.147,29.4 240.674,29.4 241.948,29.4 243.221,29.4 220.65,30.844 221.923,30.844 223.197,30.844 224.625,30.844 225.898,30.844 227.172,30.844 228.6,30.844 229.873,30.844 231.147,30.844 232.625,30.844 233.898,30.844 235.172,30.844 236.575,30.844 237.848,30.844 239.122,30.844 240.674,30.844 241.948,30.844 243.221,30.844 216.764,30.853 218.037,30.853 219.311,30.853 216.764,32.157 218.037,32.157 219.311,32.157 220.65,32.147 221.923,32.147 223.197,32.147 224.625,32.147 225.898,32.147 227.172,32.147 228.6,32.147 229.873,32.147 231.147,32.147 232.625,32.147 233.898,32.147 235.172,32.147 236.575,32.147 237.848,32.147 239.122,32.147 240.674,32.147 241.948,32.147 243.221,32.147 216.764,33.46 218.037,33.46 219.311,33.46 220.65,33.45 221.923,33.45 223.197,33.45 224.625,33.45 225.898,33.45 227.172,33.45 228.6,33.45 229.873,33.45 231.147,33.45 232.625,33.45 233.898,33.45 235.172,33.45 236.575,33.45 237.848,33.45 239.122,33.45 240.674,33.45 241.948,33.45 243.221,33.45 201.55,44.952 226,44.952 235.45,44.952 199.8,45.782 203.25,45.782 224.25,45.782 227.7,45.782 233.7,45.782 237.15,45.782 199.8,48.026 203.25,48.026 224.25,48.026 227.7,48.026 233.7,48.026 237.15,48.026 201.55,48.907 226,48.907 235.45,48.907 129.425,50.431 140.55,50.617 141.65,50.617 152.415,50.7 153.515,50.7 129.425,51.313 140.55,51.499 141.65,51.499 152.415,51.582 153.515,51.582 140.55,53.69 141.65,53.69 152.415,53.773 153.515,53.773 129.425,53.959 140.55,54.572 141.65,54.572 152.415,54.655 153.515,54.655 129.425,54.841 129.488,56.771 140.55,56.79 141.65,56.79 152.415,56.874 153.515,56.874 129.488,57.653 140.55,57.672 141.65,57.672 152.415,57.755 153.515,57.755 129.438,59.872 140.5,60.085 141.6,60.085 152.365,60.168 153.465,60.168 129.438,60.754 140.5,60.967 141.6,60.967 152.365,61.05 153.465,61.05 201.55,62.125 225.91,62.125 235.45,62.125 203.25,62.954 224.16,62.954 227.61,62.954 233.7,62.954 237.15,62.954 203.25,65.198 224.16,65.198 227.61,65.198 233.7,65.198 237.15,65.198 201.55,66.079 225.91,66.079 235.45,66.079
VBUS: R117.2 R122.2 R123.2 R124.2 TP11.1 TP12.1 U6.2
  other v1: 55.85,21.774 56.685,21.774 55.85,22.656 56.685,22.656 55.85,24.642 56.685,24.642 55.85,25.524 56.685,25.524 55.85,27.288 56.685,27.288 35.404,27.459 36.285,27.459 37.167,27.459 38.049,27.459 38.931,27.459 39.813,27.459 40.695,27.459 41.577,27.459 55.85,28.17 56.685,28.17 35.404,28.559 36.285,28.559 37.167,28.559 38.049,28.559 38.931,28.559 39.813,28.559 40.695,28.559 41.577,28.559 35.404,29.559 36.285,29.559 37.167,29.559 38.049,29.559 38.931,29.559 39.813,29.559 40.695,29.559 41.577,29.559 35.404,30.584 36.285,30.584 37.167,30.584 38.049,30.584 38.931,30.584 39.813,30.584 40.695,30.584 41.577,30.584 35.391,31.5 36.273,31.5 37.155,31.5 38.037,31.5 38.919,31.5 39.801,31.5 40.683,31.5 41.564,31.5 35.391,32.6 36.273,32.6 37.155,32.6 38.037,32.6 38.919,32.6 39.801,32.6 40.683,32.6 41.564,32.6 35.391,33.6 36.273,33.6 37.155,33.6 38.037,33.6 38.919,33.6 39.801,33.6 40.683,33.6 41.564,33.6 35.391,34.625 36.273,34.625 37.155,34.625 38.037,34.625 38.919,34.625 39.801,34.625 40.683,34.625 41.564,34.625 46.975,70.893 48.075,70.893 49.075,70.893 50.1,70.893 46.975,71.775 48.075,71.775 49.075,71.775 50.1,71.775 46.975,72.657 48.075,72.657 49.075,72.657 50.1,72.657 46.975,73.539 48.075,73.539 49.075,73.539 50.1,73.539 44.85,75.054 45.95,75.054 46.95,75.054 47.975,75.054 44.85,75.936 45.95,75.936 46.95,75.936 47.975,75.936 44.85,76.818 45.95,76.818 46.95,76.818 47.975,76.818 44.85,77.7 45.95,77.7 46.95,77.7 47.975,77.7
VIN: C1.1 C3.1 C6.1 J5.1 J5.3 J5.4 J5.6 R1.1 R4.2 R43.1 R127.1 U6.1 VIN.1 | length 135.6
  Layer 2 w0.5: -2.138,72.698 -4.05,74.609 -4.05,115.75 -1.125,118.675 v2(15.375,118.675)
  Layer 3 w0.6: v1(-0.939,69.272) -1.262,69.272 -3.712,71.722 -3.712,115.913 -1.425,118.2 7.379,118.2 12.404,123.225 VIN.1@12.729,123.225
  Bottom Layer w0.5: v2(15.375,118.675) 18.5,118.675 R43.1@18.879,118.296
  other v1: -0.125,21.336 0.875,21.336 1.975,21.336 8.075,21.336 9.075,21.336 10.175,21.336 11.091,21.349 12.116,21.349 -0.125,22.218 0.875,22.218 1.975,22.218 8.075,22.218 9.075,22.218 10.175,22.218 11.091,22.231 12.116,22.231 -0.125,23.1 0.875,23.1 1.975,23.1 8.075,23.1 9.075,23.1 10.175,23.1 11.091,23.112 12.116,23.112 27.16,27.459 28.042,27.459 28.924,27.459 29.806,27.459 30.688,27.459 31.569,27.459 32.451,27.459 33.333,27.459 27.16,28.559 28.042,28.559 28.924,28.559 29.806,28.559 30.688,28.559 31.569,28.559 32.451,28.559 33.333,28.559 27.16,29.559 28.042,29.559 28.924,29.559 29.806,29.559 30.688,29.559 31.569,29.559 32.451,29.559 33.333,29.559 27.16,30.584 28.042,30.584 28.924,30.584 29.806,30.584 30.688,30.584 31.569,30.584 32.451,30.584 33.333,30.584 27.147,31.5 28.029,31.5 28.911,31.5 29.793,31.5 30.675,31.5 31.557,31.5 32.439,31.5 33.321,31.5 27.147,32.6 28.029,32.6 28.911,32.6 29.793,32.6 30.675,32.6 31.557,32.6 32.439,32.6 33.321,32.6 27.147,33.6 28.029,33.6 28.911,33.6 29.793,33.6 30.675,33.6 31.557,33.6 32.439,33.6 33.321,33.6 27.147,34.625 28.029,34.625 28.911,34.625 29.793,34.625 30.675,34.625 31.557,34.625 32.439,34.625 33.321,34.625 10.458,38.918 8.715,39.218 12.065,39.211 7.718,40.386 13.508,40.393 19.33,41.518 20.212,41.518 7.233,42.068 13.858,42.068 19.33,42.543 20.212,42.543 7.695,43.861 13.533,43.868 8.808,44.786 12.158,44.793 10.458,45.021 -0.86,63.975 0.208,64.032 1.275,64.025 -0.86,65.032 0.208,65.032 1.325,65.025 -0.86,66.132 0.208,66.132 1.325,66.132 0.208,67.098 -0.939,67.144 1.325,67.144 -0.939,68.208 0.208,68.244
  other v4: 4.75,22.175
VMID: C4.1 C5.1 C56.1 R1.2 R5.2 R16.2 R104.1 R127.2 R129.2 R132.1 R133.1 VMID.1 | length 61.9
  Top Layer w0.254: 14.425,71.4 15.746,70.079 VMID.1@16.193,70.079
  Top Layer w0.5: v2(16.9,120.08) 17.095,120.08 R104.1@18.879,118.296
  Layer 2 w0.254: 14.175,72.025 14.247,72.025 VMID.1@16.193,70.079
  Layer 4 w0.5: -0.725,86.325 -3.725,89.325 -3.725,117.425 -1.07,120.08 v2(16.9,120.08)
  other v1: 8.023,71.214 8.905,71.214 11.525,71.214 12.407,71.214 8.023,72.239 8.905,72.239 11.525,72.239 12.407,72.239 5.675,74.275 6.557,74.275 5.675,75.3 6.557,75.3 3.25,76.65 4.132,76.65 16.593,77.167 17.475,77.167 3.25,77.675 4.132,77.675 16.593,78.192 17.475,78.192 10.358,80.943 16.593,81.025 17.475,81.025 11.965,81.236 8.615,81.243 16.593,82.05 17.475,82.05 7.618,82.411 13.408,82.418 0.225,82.55 1.107,82.55 0.225,83.575 1.107,83.575 7.133,84.093 13.758,84.093 7.595,85.886 13.433,85.893 8.708,86.811 12.058,86.818 10.358,87.046
VMID1: R19.1 R26.1 R118.1 R120.1 R121.1 R126.1 R132.2 R133.2 TP13.1 TP14.1
  other v1: 54.165,41.161 55,41.161 54.165,42.043 55,42.043 54.165,44.029 55,44.029 65.074,44.216 66.174,44.216 67.174,44.216 54.165,44.911 55,44.911 65.074,45.098 66.174,45.098 67.174,45.098 65.074,45.98 66.174,45.979 54.165,46.675 55,46.675 54.165,47.557 55,47.557 30.325,77.876 31.207,77.876 30.325,78.901 31.207,78.901 30.35,82.386 31.232,82.386 35.951,83.399 37.051,83.399 38.051,83.399 39.076,83.399 30.35,83.411 31.232,83.411 32.892,83.411 33.892,83.411 34.917,83.411 39.992,83.411 35.951,84.28 37.051,84.28 38.051,84.28 39.076,84.28 32.892,84.293 33.892,84.293 34.917,84.293 39.992,84.293 32.892,85.175 33.892,85.175 34.917,85.175 35.951,85.162 37.051,85.162 38.051,85.162 39.076,85.162 39.992,85.175
VMID2: R26.2 R117.1 R118.2 R122.1 R123.1 R124.1 TP5.1 TP6.1
  other v1: 73.74,50.325 74.84,50.325 75.84,50.325 73.74,51.207 74.84,51.207 75.84,51.207 73.74,52.088 74.84,52.088 75.84,52.088 55.5,79.861 56.6,79.861 57.6,79.861 55.5,80.743 56.6,80.743 57.6,80.743 55.5,81.625 56.6,81.625 57.6,81.625 54.5,83.136 55.6,83.136 56.6,83.136 54.5,84.018 55.6,84.018 56.6,84.018 54.5,84.9 55.6,84.9 56.6,84.9
VOUT: J13.1 J13.3 pad.3@132.922,5.61 pad.3@132.922,6.88 R47.1 | length 17.3
  Bottom Layer w0.254: R47.1@116.555,10.539 126.385,10.539 130.044,6.88 131.115,6.88 ; J13.3@131.915,5.61 J13.1@131.915,6.88
VPRI+: pad.1@105.403,100.312 T1.11
  other v1: 98.309,95.25 99.309,95.25 100.502,95.25 101.502,95.25 98.309,96.2 99.309,96.2 100.502,96.2 101.502,96.2 100.502,97.608 101.502,97.608 98.309,97.679 99.309,97.679 100.502,98.558 101.502,98.558 98.309,98.629 99.309,98.629 98.309,99.911 99.309,99.911 100.502,99.911 101.502,99.911 98.309,100.861 99.309,100.861 100.502,100.861 101.502,100.861 98.309,102.125 99.309,102.125 100.502,102.125 101.502,102.125 98.309,103.075 99.309,103.075 100.502,103.075 101.502,103.075
VSNS_OUTN: R61.2 U9.10 | length 134.7
  Layer 4 w0.254: v2(41.318,114.166) 41.318,115.753 42.255,116.69 48.793,116.69 58.3,126.197 111.903,126.197 114.787,123.313 114.787,75.964 111.865,73.043 v2(110.2,73.043)
  Bottom Layer w0.254: v2(110.2,73.043) R61.2@111.182,73.043
VSNS_OUTN_2: R60.2 U12.6 | length 126.5
  Top Layer w0.254: U12.6@43.468,111.631 48.235,111.631 v2(48.306,111.56)
  Layer 2 w0.254: v2(48.306,111.56) 49.679,112.933 49.679,114.353 61.876,126.55 111.227,126.55 114.679,123.098 114.679,83.036 111.862,80.218 v2(110.2,80.218)
  Bottom Layer w0.254: v2(110.2,80.218) R60.2@111.261,80.218
VSNS_OUTP: R66.2 U9.11 | length 140.5
  Layer 4 w0.254: v2(41.318,112.896) 40.6,113.614 40.6,116.092 41.818,117.31 48.306,117.31 57.822,126.826 112.371,126.826 115.426,123.771 115.426,75.669 v2(110.2,70.443)
  Bottom Layer w0.254: v2(110.2,70.443) R66.2@111.182,70.443
VSNS_OUTP_2: R65.2 U12.7 | length 128.8
  Top Layer w0.254: U12.7@43.468,112.901 48.301,112.901 v2(48.306,112.896)
  Layer 2 w0.254: v2(48.306,112.896) 48.306,113.902 61.596,127.192 111.483,127.192 115.3,123.375 115.3,82.797 v2(110.2,77.697)
  Bottom Layer w0.254: v2(110.2,77.697) R65.2@111.261,77.697
pads on no net: J1.2 J1.5 J1.6 J1.10 J2.1 J2.5 J2.9 J3.2 J3.6 J3.10 J6.2 J6.4 J6.6 J6.10 J6.12 J6.14 J7.1 J7.2 J8.1 J8.2 J8.3 J8.4 J8.5 J8.6 J8.8 J8.17 J8.23 J8.27 J8.29 J8.31 J8.32 J8.33 J8.34 J8.36 J8.37 J8.39 J8.40 J8.41 J8.42 J8.43 J8.44 J8.45 J8.62 J8.64 J8.66 J8.71 J8.73 J8.76 J8.78 J8.86 J8.99 J8.101 J8.103 J8.105 J8.107 J8.109 J8.115 J8.116 J8.118 J8.181 J8.182 J8.185 J8.186 J9.61 J9.62 J9.122 J9.123 J9.124 J9.126 J9.127 J9.128 J9.130 J9.131 J9.132 J9.134 J9.136 J9.137 J9.138 J9.139 J9.140 J9.141 J9.142 J9.143 J9.144 J9.145 J9.146 J9.147 J9.148 J9.149 J9.150 J9.151 J9.152 J9.153 J9.154 J9.155 J9.156 J9.159 J9.160 J9.161 J9.162 J9.163 J9.164 J9.165 J9.166 J9.167 J9.168 J9.169 J9.170 J9.174 J9.176 J10.1 J10.4 J10.8 J10.9 J11.1 J11.2 LBL1.0 T1.1 T1.3 T1.5 T1.6 T1.7 T1.8 T1.9 T1.10 U1.7 U2.7 U3.11 U6.5 U7.4
copper on no net:
  other v2: 101.637,122.188 102.935,122.188 104.19,122.188 106.745,122.188 108.003,122.188 109.285,122.188

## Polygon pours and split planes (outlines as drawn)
AGND on Top Layer "TOP_LAYER_AGND_P096" (solid, remove dead copper, pour order 96): 43 vertices, not listed, extent 47.518,0.825 246.65,129.2
AGND on Top Layer "TOP_LAYER_AGND_P097" (solid, remove dead copper, pour order 97): 56.941,7.034 56.941,12 55.906,10.965 55.906,8.597 56.941,7.563 56.941,2.091 55.925,1.075 29.324,1.075 28.569,1.83 28.569,12.908 29.738,14.077 55.898,14.077 56.941,13.034
VPRI+ on Top Layer "TOP_LAYER_VPRI+_P154" (solid, pour order 154): 102.97,94.992 107,99.022 107,101.528 103.176,105.353 97.791,105.353 97.068,104.629 97.068,95.588 97.664,94.992
LEAD_SW_R on Top Layer "TOP_LAYER_LEAD_SW_R_P152" (solid, pour order 152): 68.637,105.175 68.899,105.437 72.298,105.437 91.788,105.437 93.175,104.05 93.175,95.425 92.75,95 88.323,94.973 81.2,87.85 68.931,87.85 68.637,88.144
VBUS on Top Layer "TOP_LAYER_VBUS_P000" (solid, pour order 0): 18 vertices, not listed, extent 34.725,20.975 62.4,80.182
VIN on Top Layer "TOP_LAYER_VIN_P002" (solid, pour order 2): 9.464,46.139 6.582,43.257 1.057,43.257 -1.502,40.698 -1.499,17.732 -0.292,16.525 14.625,16.525 24.625,26.525 33.025,26.525 34.04,27.54 34.04,43.292 31.193,46.139
VMID1 on Top Layer "TOP_LAYER_VMID1_P088" (solid, pour order 88): 53.025,41.551 53.901,40.675 70.2,40.675 71.597,42.072 71.597,44.055 66.027,49.625 63.6,49.625 61.789,47.814 53.539,47.814 53.025,47.3
VMID2 on Top Layer "TOP_LAYER_VMID2_P113" (solid, pour order 113): 50.012,82.447 50.012,83.887 51.475,85.35 66.725,85.35 77.061,75.014 77.061,49.511 74.466,46.916 73.393,46.916 68.425,51.883 68.425,71.839 63.854,76.411 56.049,76.411
BIAS_VIN on Top Layer "TOP_LAYER_BIAS_VIN_P132" (solid, pour order 132): 134.59,129.15 143.825,129.15 144.425,128.55 144.425,118.379 143.975,117.929 134.897,117.929 134.22,118.606 134.22,128.716 134.341,128.836
DGND on Top Layer "TOP_LAYER_DGND_P138" (solid, remove dead copper, pour order 138): 19 vertices, not listed, extent 214.821,42.7 246.7,80.247
VBAT on Top Layer "TOP_LAYER_VBAT_P137" (solid, remove dead copper, pour order 137): 18 vertices, not listed, extent 214.65,31.975 246.65,67.325
BIAS_HS_12V on Top Layer "TOP_LAYER_BIAS_HS_12V_P114" (solid, pour order 114): 40.625,118.814 40.625,124.532 41.143,125.05 46.143,125.05 46.675,124.518 46.675,118.607 46.018,117.95 41.489,117.95
AGND on Top Layer "TOP_LAYER_AGND_P095" (solid, pour order 95): 40.843,115.792 41.392,116.341 47.518,116.341 47.893,115.966 47.893,109.19 46.218,107.516 41.68,107.516 40.843,108.353
AGNDP on Top Layer "TOP_LAYER_AGNDP_P094" (solid, pour order 94): 19 vertices, not listed, extent 23.885,107.006 34.918,116.141
PGND on Top Layer "TOP_LAYER_PGND_P049" (solid, pour order 49): 32 vertices, not listed, extent -1.525,88.991 61.475,116.725
VMID on Top Layer "TOP_LAYER_VMID_P070" (solid, pour order 70): 12.55,87.35 15.3,84.6 18.362,84.6 18.588,84.375 18.588,74.291 17.968,73.671 13.372,69.075 7.022,69.075 -1.696,77.793 -1.696,86.378 -0.724,87.35 8.556,87.35
NetC1_2 on Top Layer "TOP_LAYER_NETC1_2_P069" (solid, pour order 69): 7.996,65.382 3.742,61.128 3.742,50.495 4.26,49.978 7.219,49.978 9.472,47.725 21.674,47.725 22.48,48.531 22.48,56.495 13.593,65.382
PGND on Top Layer "TOP_LAYER_PGND_P055" (solid, pour order 55): 20.7,65.325 25.125,60.9 25.9,60.9 26.3,61.3 26.3,66.025 25.85,66.475 21.3,66.475 20.7,65.875
VIN on Top Layer "TOP_LAYER_VIN_P054" (solid, pour order 54): -1.493,63.657 -1.493,70.018 -1.024,70.487 -0.832,70.515 2.189,67.493 2.189,63.657
VMID1 on Top Layer "TOP_LAYER_VMID1_P050" (solid, pour order 50): 29.225,83.625 29.225,77.85 29.825,77.25 34.726,77.25 40.655,83.179 40.655,86.695 40.121,87.229 32.829,87.229
VMID2 on Top Layer "TOP_LAYER_VMID2_P036" (solid, pour order 36): 49.775,82.575 55.94,76.411 61.029,76.411 63.275,78.656 63.275,85.134 63.266,85.134 63.075,85.325 51.275,85.325 49.775,83.825
LEAD_SW on Top Layer "TOP_LAYER_LEAD_SW_P026" (solid, pour order 26): 63.275,105.027 63.685,105.437 66.838,105.437 67.169,105.106 67.169,88.899 66.884,88.67 58.902,88.67 58.231,89.341 58.275,94.925 58.775,95.425 61.725,95.425 63.275,96.975
LAG_SW on Top Layer "TOP_LAYER_LAG_SW_P001" (solid, pour order 1): 53.25,38.275 53.25,32.6 54.375,31.475 60.975,31.475 62.175,32.675 62.175,38.314 61.489,39 53.975,39
3V3 on Layer 2 "LAYER_2_3V3_P006" (solid, remove dead copper, pour order 6): 34 vertices, not listed, extent 22.275,1.075 246.95,129.225
AGND on Layer 2 "LAYER_2_AGND_P120" (solid, pour order 120): 55.475,59.245 55.475,67.05 56.05,67.625 60.75,67.625 61.3,67.075 61.3,59.37 60.705,58.775 55.891,58.775
VPRI+ on Layer 2 "LAYER_2_VPRI+_P153" (solid, pour order 153): 102.97,94.992 107,99.022 107,101.528 103.176,105.353 97.791,105.353 97.068,104.629 97.068,95.588 97.664,94.992
LEAD_SW_R on Layer 2 "LAYER_2_LEAD_SW_R_P151" (solid, pour order 151): 68.637,105.175 68.899,105.437 72.298,105.437 91.788,105.437 93.175,104.05 93.175,95.425 92.75,95 88.323,94.973 81.2,87.85 68.931,87.85 68.637,88.144
VIN on Layer 2 "LAYER_2_VIN_P052" (solid, pour order 52): 34 vertices, not listed, extent -2.636,16.525 34.04,73.225
VMID on Layer 2 "LAYER_2_VMID_P068" (solid, pour order 68): 12.55,87.35 15.3,84.6 18.362,84.6 18.588,84.375 18.588,74.291 17.968,73.671 13.372,69.075 7.022,69.075 -1.85,77.947 -1.85,86.138 -0.638,87.35 8.556,87.35
DGND on Layer 2 "LAYER_2_DGND_P136" (solid, remove dead copper, pour order 136): 17 vertices, not listed, extent 214.821,34.725 246.7,80.247
VBAT on Layer 2 "LAYER_2_VBAT_P135" (solid, remove dead copper, pour order 135): 218.88,33.655 222.325,37.1 222.325,64.75 224.9,67.325 236.625,67.325 239.225,64.725 239.225,36.875 244.125,31.975 218.85,31.975
AGNDP on Layer 2 "LAYER_2_AGNDP_P111" (solid, pour order 111): 17 vertices, not listed, extent 55.335,105.125 102.935,119.5
AGNDP on Layer 2 "LAYER_2_AGNDP_P129" (solid, pour order 129): 23.475,104.125 26.58,101.02 35.834,101.02 36.101,101.288 36.101,122.949 34.974,124.076 22.376,124.076 17.669,119.369 17.669,109.9
VMID1 on Layer 2 "LAYER_2_VMID1_P122" (solid, pour order 122): 64.875,43.724 64.612,43.987 64.612,46.137 64.875,46.4 67.5,46.4 67.675,46.225 67.675,43.904 67.496,43.724
VMID2 on Layer 2 "LAYER_2_VMID2_P121" (solid, pour order 121): 73.627,49.856 73.365,50.118 73.365,52.269 73.627,52.532 76.252,52.532 76.427,52.357 76.427,50.035 76.248,49.856
AGNDM on Layer 2 "LAYER_2_AGNDM_P112" (solid, remove dead copper, pour order 112): 111.861,115.214 109.508,117.567 108.402,117.567 107.635,116.8 107.635,115.365 110.1,112.9 110.1,95.327 80.775,66.002 68.548,53.775 56.714,53.775 56.125,53.186 56.125,49.437 56.763,48.8 65.737,48.8 111.861,94.924
PGND on Layer 2 "LAYER_2_PGND_P028" (solid, pour order 28): 30 vertices, not listed, extent -1.825,59.471 62.025,116.69
VMID1 on Layer 2 "LAYER_2_VMID1_P087" (solid, pour order 87): 53.025,41.551 53.901,40.675 61.789,40.675 61.789,47.814 53.539,47.814 53.025,47.3
VMID1 on Layer 2 "LAYER_2_VMID1_P077" (solid, pour order 77): 40.655,83.179 40.655,86.695 40.121,87.229 32.829,87.229 32.25,86.65 32.25,83.139 32.513,82.877 40.352,82.877
NetC1_2 on Layer 2 "LAYER_2_NETC1_2_P067" (solid, pour order 67): 7.996,65.382 3.742,61.128 3.742,50.495 4.26,49.978 7.219,49.978 9.472,47.725 21.674,47.725 22.48,48.531 22.48,56.495 13.593,65.382
VBUS on Layer 2 "LAYER_2_VBUS_P051" (solid, pour order 51): 20 vertices, not listed, extent 34.725,20.975 62.4,80.182
VMID2 on Layer 2 "LAYER_2_VMID2_P053" (solid, pour order 53): 49.775,82.575 55.94,76.411 61.029,76.411 63.275,78.656 63.275,85.134 63.266,85.134 62.9,85.5 51.45,85.5 49.775,83.825
LAG_SW on Layer 2 "LAYER_2_LAG_SW_P029" (solid, pour order 29): 53.25,38.275 53.25,32.6 54.375,31.475 60.975,31.475 62.175,32.675 62.175,38.314 61.489,39 53.975,39
LEAD_SW on Layer 2 "LAYER_2_LEAD_SW_P024" (solid, pour order 24): 63.275,105.027 63.685,105.437 66.838,105.437 67.169,105.106 67.169,88.419 66.6,87.85 58.975,87.85 58.225,88.6 58.275,94.925 58.775,95.425 61.725,95.425 63.275,96.975
VMID2 on Layer 3 "LAYER_3_VMID2_P123" (solid, pour order 123): 73.627,49.856 73.365,50.118 73.365,52.269 73.627,52.532 76.252,52.532 76.427,52.357 76.427,50.035 76.248,49.856
AGND on Layer 3 "Layer 1-AGND" (solid, remove dead copper, pour order 104): 34 vertices, not listed, extent 22.275,0.9 246.525,129.175
AGNDM on Layer 3 "LAYER_3_AGNDM_P160" (solid, pour order 160): 108.003,114.375 108.003,114.373 108.428,113.947 111.042,113.947 111.861,114.766 111.861,119.845 111.181,120.524 106.687,120.524 106.35,120.187 106.35,116.028
AGNDP on Layer 3 "LAYER_3_AGNDP_P159" (solid, pour order 159): 23 vertices, not listed, extent 55.063,105.125 104.75,121.075
LEAD_SW_R on Layer 3 "LAYER_3_LEAD_SW_R_P150" (solid, pour order 150): 68.637,105.175 68.899,105.437 72.298,105.437 91.788,105.437 93.175,104.05 93.175,95.425 92.75,95 88.323,94.973 81.2,87.85 68.931,87.85 68.637,88.144
VPRI+ on Layer 3 "LAYER_3_VPRI+_P147" (solid, pour order 147): 102.97,94.992 107,99.022 107,101.528 103.176,105.353 97.791,105.353 97.068,104.629 97.068,95.588 97.664,94.992
VMID1 on Layer 3 "LAYER_3_VMID1_P124" (solid, pour order 124): 64.875,43.724 64.612,43.987 64.612,46.137 64.875,46.4 67.5,46.4 67.675,46.225 67.675,43.904 67.496,43.724
VBUS on Layer 3 "LAYER_3_VBUS_P117" (solid, pour order 117): 35.925,26.517 34.789,27.653 34.789,34.915 35.724,35.85 44.875,35.85 52.166,28.559 61.1,28.559 61.947,27.713 61.947,21.647 61.4,21.1 47.725,21.1 42.308,26.517
AGNDP on Layer 3 "LAYER_3_AGNDP_P102" (solid, pour order 102): 23.475,104.125 26.58,101.02 35.37,101.02 36.101,101.751 36.101,122.949 34.974,124.076 22.376,124.076 17.669,119.369 17.669,109.9
VBUS on Layer 3 "LAYER_3_VBUS_P079" (solid, pour order 79): 44.8,69.8 50.325,69.8 53.087,72.562 53.087,73.938 47.164,79.861 45.061,79.861 44,78.8 44,70.6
